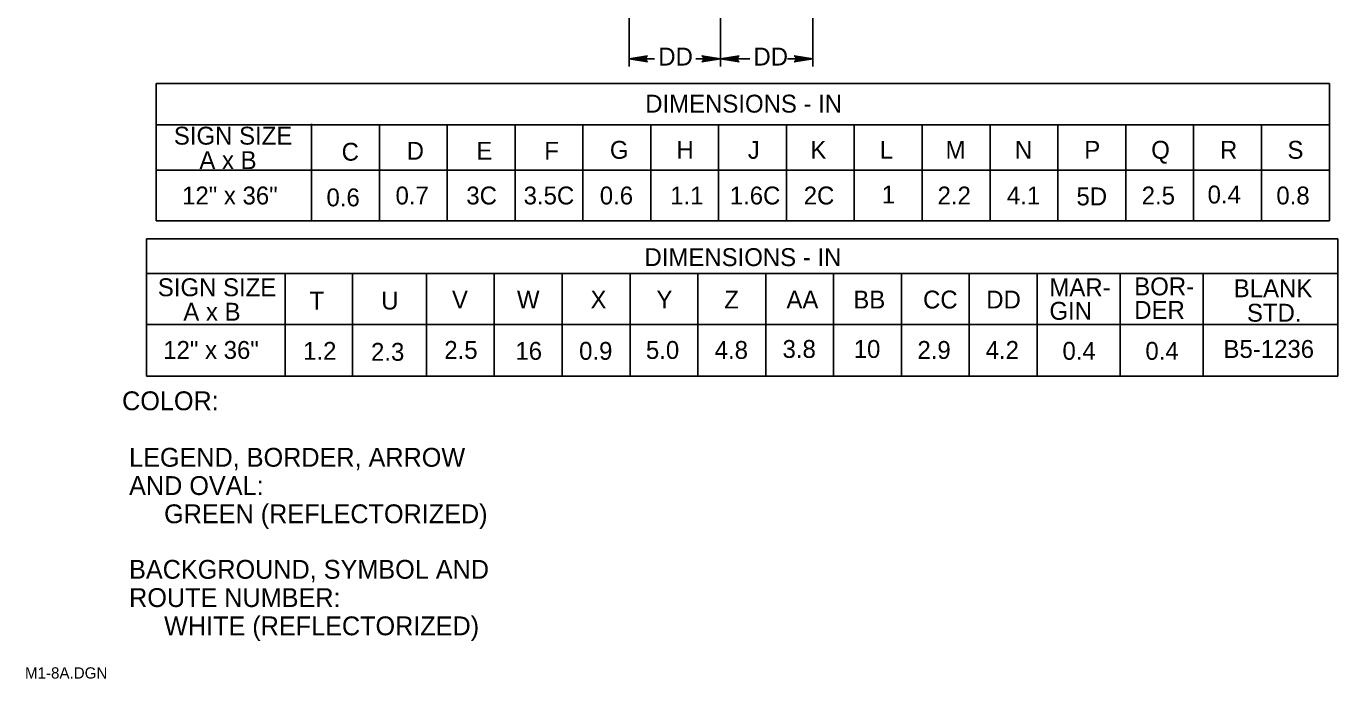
# Model space of a CAD drawing. Extents: x 0.013 to 0.193, y 0.004 to 0.259.
# Drawn here: x 0.0127 to 0.1866, y 0.0044 to 0.091 of the extents above; entities that cross this region are included whole.
import ezdxf

# ---------------------------------------------------------------- set-up
doc = ezdxf.new("R2010")
doc.units = 0
doc.layers.add('1', color=7, linetype='Continuous')
doc.layers.add('3', color=7, linetype='Continuous')

# ---------------------------------------------------------------- blocks, each defined once
blk = doc.blocks.new('RARROW')
at = {"layer": '3'}
for p, q in [((-2.156, 0.285), (-2.2665, 0.384625)), ((-2.2665, 0.384625), (0, 0)), ((0, 0), (-2.2665, -0.379125)), ((-2.156, 0.285), (-2.075625, 0.12075)), ((0, 0), (-2.156, 0.285)), ((-2.14975, -0.2705), (0, 0)), ((-2.075625, 0.12075), (0, 0)), ((0, 0), (-2.074, -0.108)), ((-2.2665, -0.379125), (-2.14975, -0.2705)), ((-2.074, -0.108), (-2.14975, -0.2705))]:
    blk.add_line(p, q, dxfattribs=at)

msp = doc.modelspace()

# ---------------------------------------------------------------- linework, layer by layer
at = {"layer": '3'}
for p, q in [((0.10475, 0.088), (0.10475, 0.12125)), ((0.09262, 0.08563), (0.09262, 0.09863)), ((0.117, 0.08563), (0.117, 0.09863)), ((0.10475, 0.08563), (0.10475, 0.088)), ((0.09262, 0.08663), (0.096, 0.08663)), ((0.1015, 0.08663), (0.10475, 0.08663)), ((0.10475, 0.08663), (0.10862, 0.08663)), ((0.11363, 0.08663), (0.117, 0.08663)), ((0.02988, 0.08338), (0.02988, 0.06513)), ((0.02991, 0.08337), (0.18553, 0.08337)), ((0.18553, 0.08337), (0.18553, 0.06512)), ((0.18553, 0.07787), (0.02991, 0.07787)), ((0.0505, 0.078), (0.0505, 0.06513)), ((0.0595, 0.07787), (0.0595, 0.06513)), ((0.0685, 0.07787), (0.0685, 0.06513)), ((0.0775, 0.07787), (0.0775, 0.06513)), ((0.0865, 0.07787), (0.0865, 0.06513)), ((0.0955, 0.07787), (0.0955, 0.06513)), ((0.1045, 0.07787), (0.1045, 0.06513)), ((0.1135, 0.07787), (0.1135, 0.06513)), ((0.1225, 0.07787), (0.1225, 0.06513)), ((0.1315, 0.07787), (0.1315, 0.06513)), ((0.1405, 0.07787), (0.1405, 0.06513)), ((0.1495, 0.07787), (0.1495, 0.06513)), ((0.1585, 0.07787), (0.1585, 0.06513)), ((0.1675, 0.07787), (0.1675, 0.06513)), ((0.1765, 0.07787), (0.1765, 0.06513)), ((0.02991, 0.07187), (0.18553, 0.07187)), ((0.02991, 0.06512), (0.18553, 0.06512)), ((0.02863, 0.06275), (0.18663, 0.06275)), ((0.02863, 0.06275), (0.02863, 0.0445)), ((0.18663, 0.06275), (0.18663, 0.0445)), ((0.18663, 0.05813), (0.02863, 0.05813)), ((0.047, 0.05813), (0.047, 0.0445)), ((0.05595, 0.05814), (0.05595, 0.04451)), ((0.06575, 0.05813), (0.06575, 0.0445)), ((0.07475, 0.05813), (0.07475, 0.0445)), ((0.08375, 0.05813), (0.08375, 0.0445)), ((0.09275, 0.05813), (0.09275, 0.0445)), ((0.10175, 0.05813), (0.10175, 0.0445)), ((0.11075, 0.05813), (0.11075, 0.0445)), ((0.11975, 0.05813), (0.11975, 0.0445)), ((0.12875, 0.05813), (0.12875, 0.0445)), ((0.13775, 0.05813), (0.13775, 0.0445)), ((0.14675, 0.05813), (0.14675, 0.0445)), ((0.15775, 0.05813), (0.15775, 0.0445)), ((0.16875, 0.05813), (0.16875, 0.0445)), ((0.02863, 0.05138), (0.18663, 0.05138)), ((0.02863, 0.0445), (0.18663, 0.0445))]:
    msp.add_line(p, q, dxfattribs=at)

# ---------------------------------------------------------------- block references
at = {"layer": '3', "xscale": 0.0010855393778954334, "yscale": 0.0010738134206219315, "rotation": 180}
for p in [(0.09262, 0.08663), (0.10475, 0.08663)]:
    msp.add_blockref('RARROW', p, dxfattribs=at)
at = {"layer": '3', "xscale": 0.0010855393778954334, "yscale": 0.0010738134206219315}
for p in [(0.10475, 0.08663), (0.117, 0.08663)]:
    msp.add_blockref('RARROW', p, dxfattribs=at)

# ---------------------------------------------------------------- texts
at = {"layer": '1'}
for s, height, p in [('COLOR:', 0.0025, (0.02538, 0.04)), (' LEGEND, BORDER, ARROW', 0.0024998, (0.02538, 0.0325)), (' AND OVAL:', 0.0025, (0.02538, 0.02875)), ('      GREEN (REFLECTORIZED)', 0.0024998, (0.02538, 0.025)), (' BACKGROUND, SYMBOL AND', 0.0024998, (0.02538, 0.01763)), (' ROUTE NUMBER:', 0.0024998, (0.02538, 0.01388)), ('      WHITE (REFLECTORIZED)', 0.0024998, (0.02538, 0.01013)), ('M1-8A.DGN', 0.0015, (0.0125, 0.00438))]:
    msp.add_text(s, height=height, dxfattribs=at).set_placement(p)
at = {"layer": '3'}
for s, height, p in [('DD', 0.002375, (0.0965, 0.08575)), ('DD', 0.002375, (0.10912, 0.08575)), ('DIMENSIONS - IN', 0.0023745, (0.09477, 0.0795)), ('SIGN SIZE', 0.002375, (0.03225, 0.07525)), ('C', 0.00237, (0.0545, 0.07312)), ('D', 0.00237, (0.06313, 0.07325)), ('E', 0.00237, (0.07237, 0.07325)), ('F', 0.00237, (0.08138, 0.07325)), ('G', 0.00237, (0.09008, 0.07337)), ('H', 0.00238, (0.09891, 0.07337)), ('J', 0.00238, (0.10837, 0.07337)), ('K', 0.00238, (0.11668, 0.07337)), ('L', 0.00238, (0.12588, 0.07337)), ('M', 0.00238, (0.1346, 0.07337)), ('N', 0.00238, (0.14379, 0.07337)), ('P', 0.00238, (0.153, 0.07337)), ('Q', 0.00238, (0.16188, 0.07337)), ('R', 0.00238, (0.171, 0.07337)), ('S', 0.00238, (0.17995, 0.07337)), ('A x B', 0.002375, (0.03563, 0.072)), ('12" x 36"', 0.002375, (0.03334, 0.06731)), ('0.7', 0.002375, (0.06165, 0.06731)), ('3C', 0.002375, (0.07104, 0.06731)), ('3.5C', 0.002375, (0.07864, 0.06731)), ('0.6', 0.002375, (0.08874, 0.06731)), ('1.1', 0.002375, (0.09808, 0.06731)), ('1.6C', 0.002375, (0.10598, 0.06731)), ('2C', 0.002375, (0.11579, 0.06731)), ('1', 0.00238, (0.12614, 0.06744)), ('2.2', 0.002375, (0.13354, 0.06731)), ('4.1', 0.002375, (0.14274, 0.06731)), ('2.5', 0.002375, (0.16062, 0.06731)), ('0.4', 0.002375, (0.16936, 0.06744)), ('0.8', 0.002375, (0.17848, 0.06731)), ('0.6', 0.002375, (0.05249, 0.06706)), ('5D', 0.002375, (0.15197, 0.06719)), ('DIMENSIONS - IN', 0.0023745, (0.09467, 0.05913)), ('SIGN SIZE', 0.002375, (0.03012, 0.05513)), ('MAR-', 0.002375, (0.14838, 0.05513)), ('BOR-', 0.002375, (0.15963, 0.05525)), ('T', 0.00238, (0.05025, 0.05335)), ('U', 0.00238, (0.05975, 0.05336)), ('V', 0.00238, (0.06913, 0.0535)), ('W', 0.00238, (0.07775, 0.0535)), ('X', 0.00238, (0.0875, 0.0535)), ('Y', 0.00238, (0.09625, 0.0535)), ('Z', 0.00238, (0.10525, 0.0535)), ('AA', 0.002375, (0.1135, 0.0535)), ('BB', 0.002375, (0.12237, 0.0535)), ('CC', 0.002375, (0.13162, 0.0535)), ('DD', 0.002375, (0.14, 0.0535)), ('BLANK', 0.002375, (0.17283, 0.055)), ('A x B', 0.002375, (0.0335, 0.05188)), ('GIN', 0.002375, (0.14838, 0.052)), ('DER', 0.002375, (0.15963, 0.05212)), ('STD.', 0.002375, (0.17458, 0.05175)), ('12" x 36"', 0.002375, (0.03084, 0.04681)), ('1.2', 0.002375, (0.04939, 0.04669)), ('2.3', 0.002375, (0.0584, 0.04656)), ('2.5', 0.002375, (0.06812, 0.04681)), ('16', 0.002375, (0.07755, 0.04669)), ('0.9', 0.002375, (0.086, 0.04669)), ('5.0', 0.002375, (0.09486, 0.04681)), ('4.8', 0.002375, (0.10398, 0.04681)), ('3.8', 0.002375, (0.11298, 0.04694)), ('10', 0.002375, (0.12242, 0.04694)), ('2.9', 0.002375, (0.13087, 0.04681)), ('4.2', 0.002375, (0.13992, 0.04681)), ('0.4', 0.002375, (0.15011, 0.04669)), ('0.4', 0.002375, (0.16111, 0.04669)), ('B5-1236', 0.002375, (0.17147, 0.04694))]:
    msp.add_text(s, height=height, dxfattribs=at).set_placement(p)

doc.saveas('drawing.dxf')
